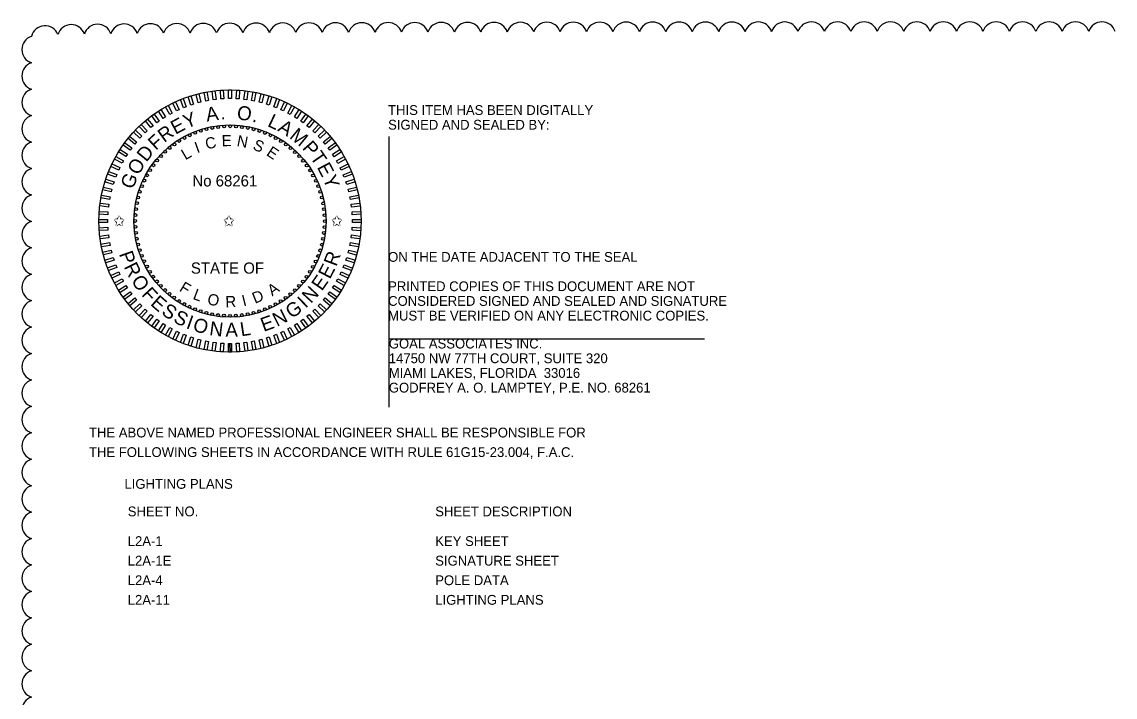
# Model space of a CAD drawing. Extents: x -811 to -790, y -2284 to -2178.
# Drawn here: x -810.98 to -803.16, y -2252.59 to -2247.76 of the extents above; entities that cross this region are included whole.
import ezdxf

# ---------------------------------------------------------------- set-up
doc = ezdxf.new("R2010")
doc.units = 0
for name, color, linetype in [('AdhocPoint_dp', 7, 'Continuous'), ('PlotBorder_dp', 7, 'Continuous'), ('ScratchEle_dp', 7, 'Continuous'), ('TextMinor', 7, 'Continuous'), ('TextMisc', 7, 'Continuous'), ('TextShtNo', 7, 'Continuous')]:
    doc.layers.add(name, color=color, linetype=linetype)

msp = doc.modelspace()

# ---------------------------------------------------------------- linework, layer by layer
at = {"layer": 'AdhocPoint_dp'}
for p, q in [((-808.3546, -2248.5853), (-808.3546, -2250.52)), ((-808.3546, -2250.03), (-806.0979, -2250.03))]:
    msp.add_line(p, q, dxfattribs=at)
at = {"layer": 'ScratchEle_dp'}
for centre, radius, start, end in [((-810.8128, -2247.8912), 0.0992, 21.52097, 166.52097), ((-810.6255, -2247.883), 0.0991, 18.44241, 163.44241), ((-810.4367, -2247.8804), 0.0991, 18.17187, 163.17187), ((-810.2478, -2247.8784), 0.0991, 18.03188, 163.03188), ((-810.0588, -2247.8768), 0.0991, 17.94243, 162.94243), ((-809.8699, -2247.8754), 0.0991, 17.8789, 162.8789), ((-809.6809, -2247.8743), 0.0991, 17.83076, 162.83076), ((-809.4919, -2247.8732), 0.0991, 17.79266, 162.79266), ((-809.3029, -2247.8723), 0.0991, 17.76151, 162.76151), ((-809.1139, -2247.8715), 0.0991, 17.73544, 162.73544), ((-808.9249, -2247.8708), 0.0991, 17.7132, 162.7132), ((-808.736, -2247.8701), 0.0991, 17.69393, 162.69393), ((-808.547, -2247.8695), 0.0991, 17.67702, 162.67702), ((-808.358, -2247.8689), 0.0991, 17.66204, 162.66204), ((-808.169, -2247.8684), 0.0991, 17.64863, 162.64863), ((-807.98, -2247.8679), 0.0991, 17.63655, 162.63655), ((-807.791, -2247.8675), 0.0991, 17.62558, 162.62558), ((-807.602, -2247.8671), 0.0991, 17.61556, 162.61556), ((-807.413, -2247.8668), 0.0991, 17.60637, 162.60637), ((-807.224, -2247.8664), 0.0991, 17.5979, 162.5979), ((-807.035, -2247.8661), 0.0991, 17.59006, 162.59006), ((-806.846, -2247.8658), 0.0991, 17.58277, 162.58277), ((-806.657, -2247.8656), 0.0991, 17.57597, 162.57597), ((-806.468, -2247.8653), 0.0991, 17.56961, 162.56961), ((-806.279, -2247.8651), 0.0991, 17.56364, 162.56364), ((-806.09, -2247.8649), 0.0991, 17.55803, 162.55803), ((-805.901, -2247.8647), 0.0991, 17.55274, 162.55274), ((-805.712, -2247.8645), 0.0991, 17.54774, 162.54774), ((-805.523, -2247.8644), 0.0991, 17.54301, 162.54301), ((-805.334, -2247.8643), 0.0991, 17.53852, 162.53852), ((-805.145, -2247.8641), 0.0991, 17.53425, 162.53425), ((-804.956, -2247.864), 0.0991, 17.53018, 162.53018), ((-804.767, -2247.8639), 0.0991, 17.52631, 162.52631), ((-804.578, -2247.8639), 0.0991, 17.52261, 162.52261), ((-804.389, -2247.8638), 0.0991, 17.51907, 162.51907), ((-804.2, -2247.8637), 0.0991, 17.51569, 162.51569), ((-804.011, -2247.8637), 0.0991, 17.51244, 162.51244), ((-803.8221, -2247.8637), 0.0991, 17.50933, 162.50933), ((-803.6331, -2247.8636), 0.0991, 17.50633, 162.50633), ((-803.4441, -2247.8636), 0.0991, 17.50345, 162.50345), ((-803.2551, -2247.8636), 0.0991, 17.50077, 162.50077), ((-810.8794, -2247.9625), 0.099, 107.5, 252.5), ((-810.8794, -2248.1514), 0.0991, 107.5, 252.5), ((-810.8794, -2248.3405), 0.0991, 107.5, 252.5), ((-810.8794, -2248.5295), 0.0991, 107.5, 252.5), ((-810.8794, -2248.7185), 0.0991, 107.5, 252.5), ((-810.8794, -2248.9075), 0.0991, 107.5, 252.5), ((-810.8794, -2249.0965), 0.0991, 107.5, 252.5), ((-810.8794, -2249.2855), 0.0991, 107.5, 252.5), ((-810.8794, -2249.4745), 0.0991, 107.5, 252.5), ((-810.8794, -2249.6635), 0.0991, 107.5, 252.5), ((-810.8794, -2249.8525), 0.0991, 107.5, 252.5), ((-810.8794, -2250.0415), 0.0991, 107.5, 252.5), ((-810.8794, -2250.2305), 0.0991, 107.5, 252.5), ((-810.8794, -2250.4195), 0.0991, 107.5, 252.5), ((-810.8794, -2250.6085), 0.0991, 107.5, 252.5), ((-810.8794, -2250.7975), 0.0991, 107.5, 252.5), ((-810.8794, -2250.9865), 0.0991, 107.5, 252.5), ((-810.8794, -2251.1755), 0.0991, 107.5, 252.5), ((-810.8794, -2251.3645), 0.0991, 107.5, 252.5), ((-810.8794, -2251.5535), 0.0991, 107.5, 252.5), ((-810.8794, -2251.7425), 0.0991, 107.5, 252.5), ((-810.8794, -2251.9315), 0.0991, 107.5, 252.5), ((-810.8794, -2252.1205), 0.0991, 107.5, 252.5), ((-810.8794, -2252.3095), 0.0991, 107.5, 252.5), ((-810.8794, -2252.4985), 0.0991, 107.50047, 252.50047), ((-810.8794, -2252.6874), 0.0991, 107.52584, 252.52584)]:
    msp.add_arc(centre, radius, start, end, dxfattribs=at)
at = {"layer": 'TextMinor'}
for radius in [0.9375, 0.6875]:
    msp.add_circle((-809.4901, -2249.1887), radius, dxfattribs=at)
at = {"layer": 'TextShtNo'}
for p, q in [((-809.5001, -2250.1262), (-809.5003, -2250.0637)), ((-809.4901, -2250.1262), (-809.4903, -2250.0637)), ((-809.4801, -2250.1261), (-809.4803, -2250.0636))]:
    msp.add_line(p, q, dxfattribs=at)
for points in [[(-809.6979, -2248.3386), (-809.7174, -2248.3436), (-809.7329, -2248.2831), (-809.7134, -2248.2781)], [(-809.6441, -2248.3272), (-809.6639, -2248.331), (-809.6756, -2248.2697), (-809.6558, -2248.2659)], [(-809.5897, -2248.3193), (-809.6097, -2248.3218), (-809.6175, -2248.2599), (-809.5975, -2248.2573)], [(-809.5349, -2248.3147), (-809.555, -2248.316), (-809.559, -2248.2537), (-809.5388, -2248.2524)], [(-809.4799, -2248.3136), (-809.5001, -2248.3136), (-809.5001, -2248.2512), (-809.4799, -2248.2512)], [(-809.425, -2248.316), (-809.4452, -2248.3147), (-809.4412, -2248.2524), (-809.4211, -2248.2537)], [(-809.3703, -2248.3218), (-809.3904, -2248.3193), (-809.3825, -2248.2573), (-809.3625, -2248.2599)], [(-809.3162, -2248.3311), (-809.336, -2248.3273), (-809.3243, -2248.2659), (-809.3045, -2248.2697)], [(-809.2626, -2248.3437), (-809.2822, -2248.3387), (-809.2667, -2248.2782), (-809.2471, -2248.2832)], [(-809.9027, -2248.417), (-809.9204, -2248.4267), (-809.9505, -2248.372), (-809.9328, -2248.3623)], [(-809.8535, -2248.3926), (-809.8717, -2248.4012), (-809.8983, -2248.3447), (-809.8801, -2248.3361)], [(-809.8028, -2248.3713), (-809.8215, -2248.3788), (-809.8445, -2248.3207), (-809.8258, -2248.3133)], [(-809.7508, -2248.3533), (-809.77, -2248.3596), (-809.7893, -2248.3002), (-809.7701, -2248.2939)], [(-809.21, -2248.3596), (-809.2292, -2248.3534), (-809.2099, -2248.294), (-809.1907, -2248.3002)], [(-809.1585, -2248.3788), (-809.1773, -2248.3714), (-809.1543, -2248.3134), (-809.1355, -2248.3208)], [(-809.1083, -2248.4013), (-809.1266, -2248.3927), (-809.1, -2248.3362), (-809.0817, -2248.3448)], [(-809.9962, -2248.4748), (-810.0125, -2248.4866), (-810.0492, -2248.4361), (-810.0329, -2248.4243)], [(-809.9504, -2248.4444), (-809.9674, -2248.4552), (-810.0009, -2248.4025), (-809.9838, -2248.3917)], [(-809.0596, -2248.4268), (-809.0773, -2248.4171), (-809.0473, -2248.3624), (-809.0296, -2248.3721)], [(-809.0127, -2248.4553), (-809.0297, -2248.4445), (-808.9962, -2248.3918), (-808.9792, -2248.4026)], [(-808.9676, -2248.4868), (-808.9839, -2248.4749), (-808.9472, -2248.4244), (-808.9308, -2248.4362)], [(-810.0817, -2248.5438), (-810.0964, -2248.5577), (-810.1392, -2248.5121), (-810.1244, -2248.4983)], [(-810.04, -2248.508), (-810.0556, -2248.5208), (-810.0954, -2248.4727), (-810.0798, -2248.4599)], [(-808.9245, -2248.5209), (-808.9401, -2248.5081), (-808.9003, -2248.46), (-808.8847, -2248.4728)], [(-808.8837, -2248.5578), (-808.8984, -2248.544), (-808.8557, -2248.4984), (-808.841, -2248.5123)], [(-810.1579, -2248.6231), (-810.1707, -2248.6386), (-810.2188, -2248.5988), (-810.206, -2248.5833)], [(-810.121, -2248.5823), (-810.1348, -2248.597), (-810.1804, -2248.5542), (-810.1665, -2248.5395)], [(-808.8453, -2248.5971), (-808.8591, -2248.5824), (-808.8136, -2248.5396), (-808.7998, -2248.5544)], [(-808.8094, -2248.6388), (-808.8223, -2248.6232), (-808.7742, -2248.5834), (-808.7613, -2248.599)], [(-810.192, -2248.6661), (-810.2039, -2248.6824), (-810.2544, -2248.6457), (-810.2426, -2248.6294)], [(-808.7762, -2248.6826), (-808.7881, -2248.6663), (-808.7376, -2248.6296), (-808.7257, -2248.6459)], [(-810.252, -2248.7582), (-810.2617, -2248.7759), (-810.3164, -2248.7458), (-810.3067, -2248.7281)], [(-810.2235, -2248.7112), (-810.2343, -2248.7283), (-810.287, -2248.6948), (-810.2762, -2248.6778)], [(-808.7459, -2248.7284), (-808.7567, -2248.7114), (-808.7039, -2248.6779), (-808.6931, -2248.695)], [(-808.7184, -2248.7761), (-808.7281, -2248.7584), (-808.6734, -2248.7283), (-808.6637, -2248.746)], [(-810.2775, -2248.8069), (-810.2861, -2248.8252), (-810.3426, -2248.7986), (-810.334, -2248.7803)], [(-808.694, -2248.8253), (-808.7026, -2248.8071), (-808.6461, -2248.7805), (-808.6375, -2248.7987)], [(-810.3192, -2248.9086), (-810.3254, -2248.9278), (-810.3848, -2248.9085), (-810.3786, -2248.8893)], [(-810.3, -2248.8571), (-810.3074, -2248.8759), (-810.3654, -2248.8529), (-810.358, -2248.8341)], [(-808.6728, -2248.876), (-808.6802, -2248.8573), (-808.6222, -2248.8343), (-808.6147, -2248.853)], [(-808.6548, -2248.928), (-808.661, -2248.9088), (-808.6016, -2248.8895), (-808.5954, -2248.9087)], [(-810.3351, -2248.9612), (-810.3401, -2248.9808), (-810.4006, -2248.9652), (-810.3956, -2248.9457)], [(-808.64, -2248.9809), (-808.6451, -2248.9614), (-808.5846, -2248.9459), (-808.5796, -2248.9654)], [(-810.357, -2249.0689), (-810.3595, -2249.0889), (-810.4215, -2249.0811), (-810.4189, -2249.0611)], [(-810.3477, -2249.0147), (-810.3515, -2249.0345), (-810.4129, -2249.0228), (-810.4091, -2249.003)], [(-808.6287, -2249.0347), (-808.6325, -2249.0149), (-808.5711, -2249.0032), (-808.5673, -2249.023)], [(-808.6207, -2249.0891), (-808.6232, -2249.0691), (-808.5613, -2249.0613), (-808.5588, -2249.0813)], [(-810.3628, -2249.1236), (-810.3641, -2249.1437), (-810.4264, -2249.1398), (-810.4251, -2249.1196)], [(-808.6162, -2249.1439), (-808.6174, -2249.1238), (-808.5551, -2249.1198), (-808.5539, -2249.14)], [(-810.3652, -2249.1785), (-810.3652, -2249.1987), (-810.4276, -2249.1987), (-810.4276, -2249.1785)], [(-808.6151, -2249.1989), (-808.6151, -2249.1787), (-808.5527, -2249.1787), (-808.5527, -2249.1989)], [(-810.3641, -2249.2335), (-810.3628, -2249.2536), (-810.4251, -2249.2575), (-810.4264, -2249.2374)], [(-810.3595, -2249.2882), (-810.357, -2249.3083), (-810.4189, -2249.3161), (-810.4215, -2249.2961)], [(-808.6233, -2249.3085), (-808.6207, -2249.2884), (-808.5588, -2249.2963), (-808.5613, -2249.3163)], [(-808.6175, -2249.2538), (-808.6162, -2249.2336), (-808.5539, -2249.2376), (-808.5551, -2249.2577)], [(-810.3516, -2249.3426), (-810.3478, -2249.3625), (-810.4091, -2249.3742), (-810.4129, -2249.3543)], [(-808.6325, -2249.3626), (-808.6287, -2249.3428), (-808.5674, -2249.3545), (-808.5712, -2249.3743)], [(-810.3402, -2249.3964), (-810.3352, -2249.416), (-810.3957, -2249.4315), (-810.4007, -2249.412)], [(-810.3255, -2249.4494), (-810.3192, -2249.4686), (-810.3786, -2249.4879), (-810.3849, -2249.4687)], [(-808.6611, -2249.4688), (-808.6548, -2249.4496), (-808.5954, -2249.4689), (-808.6017, -2249.4881)], [(-808.6451, -2249.4162), (-808.6401, -2249.3966), (-808.5796, -2249.4121), (-808.5846, -2249.4317)], [(-810.3075, -2249.5013), (-810.3, -2249.5201), (-810.3581, -2249.5431), (-810.3655, -2249.5243)], [(-808.6803, -2249.5203), (-808.6729, -2249.5015), (-808.6148, -2249.5245), (-808.6222, -2249.5433)], [(-810.2862, -2249.552), (-810.2776, -2249.5703), (-810.3341, -2249.5969), (-810.3427, -2249.5786)], [(-810.2618, -2249.6013), (-810.2521, -2249.619), (-810.3068, -2249.6491), (-810.3165, -2249.6314)], [(-808.7282, -2249.6192), (-808.7185, -2249.6015), (-808.6638, -2249.6315), (-808.6735, -2249.6492)], [(-808.7027, -2249.5705), (-808.6941, -2249.5522), (-808.6376, -2249.5788), (-808.6462, -2249.5971)], [(-810.2344, -2249.6489), (-810.2236, -2249.666), (-810.2763, -2249.6994), (-810.2871, -2249.6824)], [(-808.7568, -2249.6661), (-808.746, -2249.6491), (-808.6932, -2249.6826), (-808.704, -2249.6996)], [(-810.204, -2249.6948), (-810.1922, -2249.7111), (-810.2427, -2249.7478), (-810.2545, -2249.7315)], [(-810.1708, -2249.7386), (-810.158, -2249.7541), (-810.2061, -2249.794), (-810.2189, -2249.7784)], [(-808.8224, -2249.7543), (-808.8095, -2249.7387), (-808.7614, -2249.7785), (-808.7743, -2249.7941)], [(-808.7882, -2249.7112), (-808.7763, -2249.6949), (-808.7258, -2249.7316), (-808.7377, -2249.748)], [(-810.135, -2249.7803), (-810.1211, -2249.795), (-810.1667, -2249.8377), (-810.1805, -2249.823)], [(-810.0965, -2249.8196), (-810.0818, -2249.8334), (-810.1246, -2249.8789), (-810.1393, -2249.8651)], [(-808.8985, -2249.8335), (-808.8838, -2249.8197), (-808.8411, -2249.8652), (-808.8558, -2249.879)], [(-808.8592, -2249.7951), (-808.8454, -2249.7804), (-808.7999, -2249.8231), (-808.8137, -2249.8378)], [(-810.0557, -2249.8564), (-810.0402, -2249.8693), (-810.08, -2249.9174), (-810.0955, -2249.9045)], [(-810.0127, -2249.8906), (-809.9964, -2249.9025), (-810.0331, -2249.953), (-810.0494, -2249.9411)], [(-809.9676, -2249.922), (-809.9505, -2249.9328), (-809.984, -2249.9856), (-810.001, -2249.9748)], [(-809.0299, -2249.9329), (-809.0128, -2249.9221), (-808.9794, -2249.9749), (-808.9964, -2249.9857)], [(-808.984, -2249.9026), (-808.9677, -2249.8907), (-808.931, -2249.9412), (-808.9473, -2249.9531)], [(-808.9402, -2249.8694), (-808.9247, -2249.8565), (-808.8848, -2249.9046), (-808.9004, -2249.9175)], [(-809.9206, -2249.9506), (-809.9029, -2249.9603), (-809.933, -2250.015), (-809.9507, -2250.0053)], [(-809.8719, -2249.9761), (-809.8536, -2249.9847), (-809.8802, -2250.0412), (-809.8985, -2250.0326)], [(-809.8217, -2249.9985), (-809.8029, -2250.0059), (-809.8259, -2250.064), (-809.8447, -2250.0566)], [(-809.1775, -2250.006), (-809.1587, -2249.9986), (-809.1357, -2250.0566), (-809.1545, -2250.0641)], [(-809.1268, -2249.9848), (-809.1085, -2249.9762), (-809.0819, -2250.0327), (-809.1002, -2250.0413)], [(-809.0775, -2249.9604), (-809.0598, -2249.9507), (-809.0297, -2250.0054), (-809.0474, -2250.0151)], [(-809.7702, -2250.0177), (-809.751, -2250.024), (-809.7703, -2250.0834), (-809.7895, -2250.0771)], [(-809.7176, -2250.0337), (-809.698, -2250.0387), (-809.7136, -2250.0992), (-809.7331, -2250.0942)], [(-809.6641, -2250.0463), (-809.6443, -2250.0501), (-809.656, -2250.1114), (-809.6758, -2250.1076)], [(-809.6099, -2250.0555), (-809.5899, -2250.0581), (-809.5977, -2250.12), (-809.6177, -2250.1175)], [(-809.5552, -2250.0613), (-809.5351, -2250.0626), (-809.539, -2250.1249), (-809.5592, -2250.1237)], [(-809.5003, -2250.0637), (-809.4801, -2250.0637), (-809.4801, -2250.1261), (-809.5003, -2250.1261)], [(-809.4453, -2250.0626), (-809.4252, -2250.0614), (-809.4213, -2250.1237), (-809.4414, -2250.1249)], [(-809.3906, -2250.0581), (-809.3705, -2250.0556), (-809.3627, -2250.1175), (-809.3827, -2250.12)], [(-809.3362, -2250.0501), (-809.3163, -2250.0463), (-809.3046, -2250.1077), (-809.3245, -2250.1115)], [(-809.2824, -2250.0388), (-809.2628, -2250.0337), (-809.2473, -2250.0942), (-809.2668, -2250.0992)], [(-809.2294, -2250.024), (-809.2102, -2250.0178), (-809.1909, -2250.0772), (-809.2101, -2250.0834)]]:
    msp.add_lwpolyline(points, close=True, dxfattribs=at)
for centre in [(-809.6165, -2248.5231), (-809.5745, -2248.5165), (-809.5321, -2248.5125), (-809.4896, -2248.5112), (-809.447, -2248.5126), (-809.4047, -2248.5166), (-809.3626, -2248.5233), (-809.816, -2248.5947), (-809.7781, -2248.5754), (-809.739, -2248.5586), (-809.6989, -2248.5442), (-809.6581, -2248.5324), (-809.3211, -2248.5326), (-809.2802, -2248.5445), (-809.2402, -2248.559), (-809.2012, -2248.5759), (-809.1633, -2248.5953), (-809.9215, -2248.6663), (-809.8879, -2248.6403), (-809.8527, -2248.6164), (-809.1266, -2248.617), (-809.0915, -2248.6409), (-809.0579, -2248.667), (-810.0118, -2248.7564), (-809.9836, -2248.7245), (-809.9535, -2248.6944), (-809.026, -2248.6952), (-808.9959, -2248.7253), (-808.9678, -2248.7573), (-810.0618, -2248.8252), (-810.0379, -2248.79), (-808.9417, -2248.7909), (-808.9178, -2248.8261), (-810.1029, -2248.8997), (-810.0835, -2248.8618), (-808.8962, -2248.8628), (-808.8769, -2248.9007), (-810.1343, -2248.9788), (-810.1198, -2248.9388), (-808.86, -2248.9398), (-808.8456, -2248.9799), (-810.1555, -2249.0612), (-810.1462, -2249.0197), (-808.8338, -2249.0207), (-808.8245, -2249.0623), (-810.1662, -2249.1456), (-810.1622, -2249.1032), (-808.8179, -2249.1043), (-808.814, -2249.1467), (-810.1676, -2249.1881), (-810.1663, -2249.2307), (-808.814, -2249.2318), (-808.8127, -2249.1892), (-810.1623, -2249.273), (-808.8181, -2249.2741), (-810.1557, -2249.3151), (-810.1464, -2249.3566), (-808.8341, -2249.3577), (-808.8248, -2249.3162), (-810.1346, -2249.3975), (-810.1202, -2249.4375), (-808.8604, -2249.4386), (-808.846, -2249.3986), (-810.1034, -2249.4766), (-810.0841, -2249.5146), (-808.8967, -2249.5155), (-808.8774, -2249.4776), (-810.0624, -2249.5512), (-810.0385, -2249.5864), (-810.0125, -2249.6201), (-808.9685, -2249.6209), (-808.9424, -2249.5873), (-808.9184, -2249.5522), (-809.9844, -2249.652), (-809.9543, -2249.6821), (-809.0268, -2249.6829), (-808.9967, -2249.6528), (-809.9224, -2249.7103), (-809.8888, -2249.7364), (-809.8536, -2249.7604), (-809.1276, -2249.761), (-809.0924, -2249.7371), (-809.0587, -2249.711), (-809.817, -2249.7821), (-809.7791, -2249.8014), (-809.74, -2249.8184), (-809.7, -2249.8328), (-809.6591, -2249.8447), (-809.6176, -2249.854), (-809.3637, -2249.8543), (-809.3222, -2249.845), (-809.2813, -2249.8332), (-809.2413, -2249.8188), (-809.2022, -2249.8019), (-809.1642, -2249.7826), (-809.5756, -2249.8607), (-809.5332, -2249.8648), (-809.4901, -2249.8662), (-809.4481, -2249.8648), (-809.4058, -2249.8609)]:
    msp.add_circle(centre, 0.01, dxfattribs=at)

# ---------------------------------------------------------------- texts
at = {"layer": 'PlotBorder_dp'}
for s, p in [('THIS ITEM HAS BEEN DIGITALLY', (-808.3596, -2248.4301)), ('SIGNED AND SEALED BY:', (-808.3596, -2248.5351)), ('ON THE DATE ADJACENT TO THE SEAL', (-808.3596, -2249.4801)), ('PRINTED COPIES OF THIS DOCUMENT ARE NOT ', (-808.3596, -2249.6901)), ('CONSIDERED SIGNED AND SEALED AND SIGNATURE ', (-808.3596, -2249.7951)), ('MUST BE VERIFIED ON ANY ELECTRONIC COPIES.', (-808.3596, -2249.9001)), ('GOAL ASSOCIATES INC.', (-808.3546, -2250.1)), ('14750 NW 77TH COURT, SUITE 320', (-808.3546, -2250.205)), ('MIAMI LAKES, FLORIDA  33016', (-808.3546, -2250.31)), ('GODFREY A. O. LAMPTEY, P.E. NO. 68261', (-808.3546, -2250.415)), ('THE ABOVE NAMED PROFESSIONAL ENGINEER SHALL BE RESPONSIBLE FOR ', (-810.4987, -2250.7361)), ('THE FOLLOWING SHEETS IN ACCORDANCE WITH RULE 61G15-23.004, F.A.C.', (-810.4987, -2250.8761)), ('LIGHTING PLANS', (-810.245, -2251.1032))]:
    msp.add_text(s, height=0.07, dxfattribs=at).set_placement(p)
at = {"layer": 'TextMisc'}
for s, p in [('SHEET NO.', (-810.2215, -2251.3001)), ('SHEET DESCRIPTION', (-808.0226, -2251.3001)), ('L2A-1', (-810.2215, -2251.5123)), ('KEY SHEET', (-808.0226, -2251.5123)), ('L2A-1E', (-810.2215, -2251.6523)), ('SIGNATURE SHEET', (-808.0226, -2251.6523)), ('L2A-4', (-810.2215, -2251.7923)), ('POLE DATA', (-808.0226, -2251.7923)), ('L2A-11', (-810.2215, -2251.9323)), ('LIGHTING PLANS', (-808.0226, -2251.9323))]:
    msp.add_text(s, height=0.07, dxfattribs=at).set_placement(p)
at = {"layer": 'TextShtNo'}
for s, height, rotation, p in [('Y', 0.1, 21.06329, (-809.8021, -2248.5293)), ('A', 0.1, 8.80884, (-809.6551, -2248.4781)), ('O', 0.1, 352.18771, (-809.4449, -2248.4606)), ('L', 0.1, 334.67271, (-809.2279, -2248.5079)), ('R', 0.1, 35.92688, (-809.9609, -2248.6314)), ('E', 0.1, 28.10553, (-809.8806, -2248.5725)), ('.', 0.1, 1.04184, (-809.5575, -2248.4623)), ('.', 0.1, 343.52684, (-809.3358, -2248.4757)), ('A', 0.1, 328.40959, (-809.1552, -2248.5406)), ('F', 0.1, 42.37723, (-810.0205, -2248.6878)), ('C', 0.08, 12.20255, (-809.6579, -2248.6771)), ('E', 0.08, 0.41861, (-809.5498, -2248.6536)), ('N', 0.08, 349.29143, (-809.4455, -2248.6521)), ('M', 0.1, 320.6426, (-809.0707, -2248.5918)), ('D', 0.1, 50.8569, (-810.0886, -2248.7715)), ('I', 0.08, 20.01168, (-809.7258, -2248.7046)), ('S', 0.08, 337.02207, (-809.3325, -2248.6739)), ('E', 0.08, 325.86633, (-809.2358, -2248.7141)), ('P', 0.1, 311.19658, (-808.9784, -2248.6687)), ('O', 0.1, 59.51777, (-810.1446, -2248.8663)), ('L', 0.08, 30.40215, (-809.8093, -2248.7551)), ('T', 0.1, 304.45632, (-808.9209, -2248.7324)), ('E', 0.1, 297.63152, (-808.8707, -2248.8033)), ('G', 0.1, 68.0518, (-810.1851, -2248.967)), ('Y', 0.1, 290.58928, (-808.8281, -2248.8821)), ('P', 0.1, 289.40551, (-810.2848, -2249.4233)), ('R', 0.1, 69.5134, (-808.7299, -2249.5184)), ('R', 0.1, 296.14576, (-810.2518, -2249.5149)), ('E', 0.1, 62.47116, (-808.7761, -2249.6091)), ('O', 0.1, 303.96711, (-810.2003, -2249.6155)), ('E', 0.1, 55.42892, (-808.833, -2249.6935)), ('F', 0.1, 312.62798, (-810.1279, -2249.7176)), ('F', 0.08, 328.72408, (-809.8582, -2249.6853)), ('L', 0.08, 339.29159, (-809.7609, -2249.7443)), ('D', 0.08, 22.01279, (-809.312, -2249.7806)), ('A', 0.08, 34.49917, (-809.1883, -2249.7281)), ('N', 0.1, 47.17876, (-808.9123, -2249.7825)), ('E', 0.1, 319.07833, (-810.0645, -2249.7859)), ('O', 0.08, 349.68206, (-809.6562, -2249.7841)), ('R', 0.08, 2.33977, (-809.5217, -2249.806)), ('I', 0.08, 14.20366, (-809.3941, -2249.7993)), ('G', 0.1, 35.11153, (-809.0492, -2249.8902)), ('I', 0.1, 43.64556, (-808.9499, -2249.817)), ('S', 0.1, 326.12056, (-809.9869, -2249.8518)), ('S', 0.1, 333.193, (-809.9015, -2249.9079)), ('N', 0.1, 26.86136, (-809.1544, -2249.9462)), ('I', 0.1, 340.26543, (-809.8098, -2249.9531)), ('O', 0.1, 343.79863, (-809.7621, -2249.9714)), ('N', 0.1, 352.45949, (-809.6411, -2250.0034)), ('A', 0.1, 0.70966, (-809.5227, -2250.0166)), ('L', 0.1, 8.47665, (-809.4105, -2250.0134)), ('E', 0.1, 19.81912, (-809.2498, -2249.9817))]:
    msp.add_text(s, height=height, rotation=rotation, dxfattribs=at).set_placement(p)
for s, p in [('No 68261', (-809.7591, -2248.9414)), ('✩', (-810.3251, -2249.2266)), ('✩', (-809.5404, -2249.2266)), ('✩', (-808.7685, -2249.2266)), ('STATE OF', (-809.7698, -2249.5649))]:
    msp.add_text(s, height=0.08, dxfattribs=at).set_placement(p)

doc.saveas('drawing.dxf')
